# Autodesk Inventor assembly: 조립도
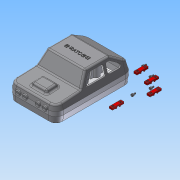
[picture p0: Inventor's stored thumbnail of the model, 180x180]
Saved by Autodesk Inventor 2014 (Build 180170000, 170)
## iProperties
Created: 2015-05
Part Number: 조립도
Document SubType Name: Assembly
Designer: Administrator
Author: Administrator
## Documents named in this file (7)
- C:\Documents and Settings\Administrator\바탕 화면\450508V1035\조립도.iam
- C:\Documents and Settings\Administrator\바탕 화면\450508V1035\본체.ipt
- C:\Documents and Settings\Administrator\바탕 화면\450508V1035\커버.ipt
- C:\Documents and Settings\Administrator\바탕 화면\450508V1035\바퀴.ipt
- C:\Documents and Settings\Administrator\바탕 화면\450508V1035\M4x10.ipt
- C:\Documents and Settings\Administrator\바탕 화면\450508V1035\바퀴고정부.ipt
- C:\Documents and Settings\Administrator\바탕 화면\450508V1035\M2x4.ipt
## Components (8 placed, 2 different names)
1. M4x10:1
2. M2x4:1
3. M4x10:2
4. M2x4:2
5. M4x10:3
6. M2x4:3
7. M4x10:4
8. M2x4:4
